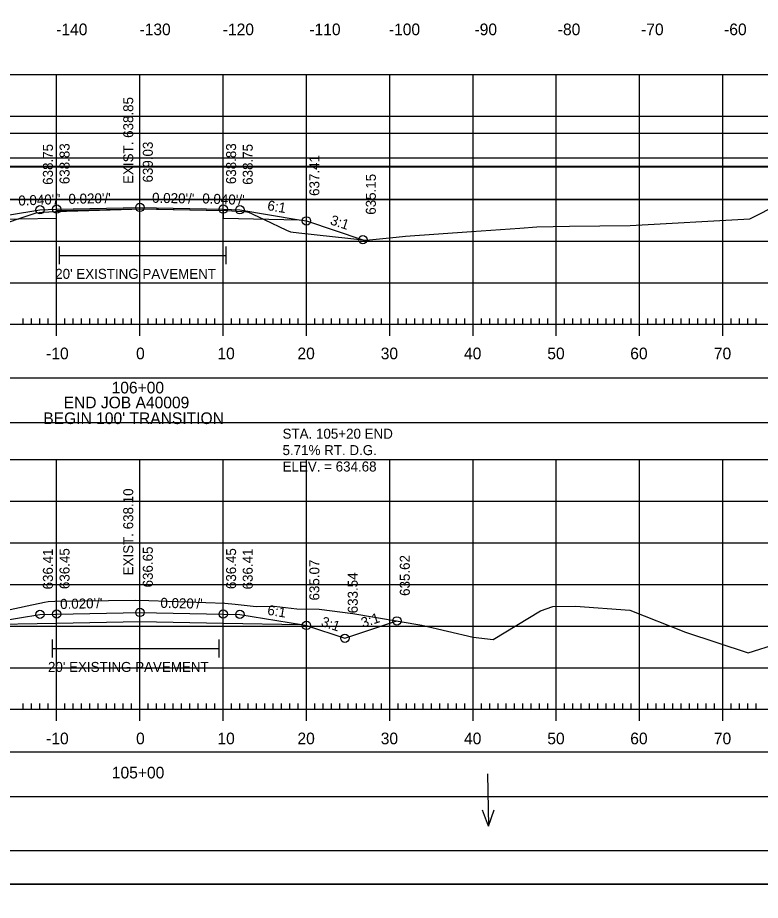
# Model space of a CAD drawing. Extents: x 1381471 to 1382703, y 370300 to 371487.
# Drawn here: x 1381990.1 to 1382079.3, y 370972.4 to 371078.4 of the extents above; entities that cross this region are included whole.
import ezdxf

# ---------------------------------------------------------------- set-up
doc = ezdxf.new("R2010")
doc.units = 0
for name, color, linetype in [('Level 16', 7, 'Continuous'), ('Level 18', 7, 'Continuous'), ('Level 2', 7, 'Continuous'), ('Level 20', 7, 'Continuous'), ('Level 21', 7, 'Continuous'), ('Level 22', 7, 'Continuous'), ('Level 26', 7, 'Continuous'), ('Level 4', 7, 'Continuous'), ('Level 40', 7, 'Continuous'), ('Level 41', 7, 'Continuous'), ('Level 42', 7, 'Continuous'), ('Level 45', 7, 'Continuous'), ('Level 5', 7, 'Continuous'), ('Level 6', 7, 'Continuous')]:
    doc.layers.add(name, color=color, linetype=linetype)

msp = doc.modelspace()

# ---------------------------------------------------------------- linework, layer by layer
at = {"layer": 'Level 16'}
for p, q in [((1381995.09, 371050.89), (1381995.09, 371048.75)), ((1382015.09, 371050.89), (1382015.09, 371048.75)), ((1381995.09, 371049.82), (1382015.09, 371049.82)), ((1381994.23, 371003.68), (1381994.23, 371001.54)), ((1382014.23, 371003.68), (1382014.23, 371001.54)), ((1381994.23, 371002.61), (1382014.23, 371002.61))]:
    msp.add_line(p, q, dxfattribs=at)
at = {"layer": 'Level 18'}
for points in [[(1381987.31, 371053.25), (1381990.38, 371054.28), (1381992.31, 371054.94), (1381993.02, 371055.01), (1381994.62, 371055.1), (1381998.64, 371055.21), (1382005.09, 371055.4), (1382012.74, 371055.24), (1382015.21, 371055.19), (1382017.6, 371055.05), (1382017.73, 371055.04), (1382019.71, 371054.11), (1382022.37, 371052.85), (1382022.84, 371052.64), (1382023.84, 371052.53), (1382031.92, 371051.66), (1382035.53, 371052.01), (1382036.68, 371052.13), (1382044.57, 371052.68), (1382050.4, 371053.09), (1382052.42, 371053.26), (1382056.35, 371053.34), (1382063.66, 371053.4), (1382078.02, 371054.19), (1382088.62, 371059.56)], [(1381986.4, 371006.7), (1381991.25, 371007.74), (1381993.31, 371008.17), (1381993.77, 371008.25), (1381994.56, 371008.27), (1382004.23, 371008.41), (1382005.83, 371008.36), (1382014.95, 371008.04), (1382016.22, 371007.92), (1382018.73, 371007.66), (1382020.88, 371007.68), (1382023.63, 371007.35), (1382026.3, 371007.31), (1382030.32, 371006.81), (1382038.62, 371005.42), (1382044.77, 371003.97), (1382047.2, 371003.69), (1382052.87, 371007.13), (1382054.36, 371007.64), (1382057.06, 371007.69), (1382063.6, 371007.21), (1382070.27, 371004.56), (1382077.82, 371002.09), (1382081.37, 371003.19)]]:
    msp.add_lwpolyline(points, dxfattribs=at)
at = {"layer": 'Level 2'}
for points in [[(1381985.66, 371054.11), (1381994.76, 371054.29), (1381994.77, 371055.21), (1382004.77, 371055.41), (1382014.77, 371055.2), (1382014.78, 371054.29), (1382023.91, 371054.1)], [(1381985.39, 371005.47), (1381994.77, 371005.66), (1382004.77, 371005.86), (1382014.77, 371005.66), (1382024.16, 371005.47)]]:
    msp.add_lwpolyline(points, dxfattribs=at)
at = {"layer": 'Level 20'}
for points in [[(1381973.41, 371053.43), (1381978.3, 371051.8), (1381984.77, 371053.96), (1381985.66, 371054.11), (1381992.77, 371055.29), (1381994.77, 371055.37), (1382004.77, 371055.57), (1382014.77, 371055.37), (1382016.77, 371055.29), (1382023.91, 371054.1), (1382024.77, 371053.96), (1382031.55, 371051.7)], [(1381968.79, 371006.89), (1381979.07, 371003.47), (1381984.77, 371005.37), (1381985.39, 371005.47), (1381992.77, 371006.7), (1381994.77, 371006.74), (1382004.77, 371006.94), (1382014.77, 371006.74), (1382016.77, 371006.7), (1382024.16, 371005.47), (1382024.77, 371005.37), (1382029.38, 371003.83), (1382035.63, 371005.92)]]:
    msp.add_lwpolyline(points, dxfattribs=at)
at = {"layer": 'Level 22'}
for p, q in [((1381864.77, 371071.54), (1382144.77, 371071.54)), ((1381994.77, 371041.54), (1381994.77, 371071.54)), ((1382004.77, 371041.54), (1382004.77, 371071.54)), ((1382014.77, 371041.54), (1382014.77, 371071.54)), ((1382024.77, 371041.54), (1382024.77, 371071.54)), ((1382034.77, 371041.54), (1382034.77, 371071.54)), ((1382044.77, 371041.54), (1382044.77, 371071.54)), ((1382054.77, 371041.54), (1382054.77, 371071.54)), ((1382064.77, 371041.54), (1382064.77, 371071.54)), ((1382074.77, 371041.54), (1382074.77, 371071.54)), ((1381864.77, 371066.54), (1382144.77, 371066.54)), ((1381864.77, 371061.54), (1382144.77, 371061.54)), ((1381864.77, 371056.54), (1382144.77, 371056.54)), ((1381864.77, 371051.54), (1382144.77, 371051.54)), ((1381864.77, 371046.54), (1382144.77, 371046.54)), ((1381864.77, 371041.54), (1382144.77, 371041.54)), ((1381864.77, 371025.3), (1382144.77, 371025.3)), ((1381994.77, 370995.3), (1381994.77, 371025.3)), ((1382004.77, 370995.3), (1382004.77, 371025.3)), ((1382014.77, 370995.3), (1382014.77, 371025.3)), ((1382024.77, 370995.3), (1382024.77, 371025.3)), ((1382034.77, 370995.3), (1382034.77, 371025.3)), ((1382044.77, 370995.3), (1382044.77, 371025.3)), ((1382054.77, 370995.3), (1382054.77, 371025.3)), ((1382064.77, 370995.3), (1382064.77, 371025.3)), ((1382074.77, 370995.3), (1382074.77, 371025.3)), ((1381864.77, 371020.3), (1382144.77, 371020.3)), ((1381864.77, 371015.3), (1382144.77, 371015.3)), ((1381864.77, 371010.3), (1382144.77, 371010.3)), ((1381864.77, 371005.3), (1382144.77, 371005.3)), ((1381864.77, 371000.3), (1382144.77, 371000.3)), ((1381864.77, 370995.3), (1382144.77, 370995.3))]:
    msp.add_line(p, q, dxfattribs=at)
at = {"layer": 'Level 26'}
for p, q in [((1381834.37, 370974.31), (1382167.7, 370974.31)), ((1381834.37, 370974.3), (1382167.7, 370974.3))]:
    msp.add_line(p, q, dxfattribs=at)
for points in [[(1381834.36, 371187.64), (1382167.7, 371187.64), (1382167.7, 370974.3), (1381834.36, 370974.3)], [(1382080.69, 371183.75), (1382100.31, 371183.75), (1382100.31, 371173.87), (1382116.42, 371173.87), (1382139.62, 371173.87), (1382139.62, 371141.2), (1382162.83, 371141.2), (1382162.95, 370978.29), (1381846.77, 370978.29), (1381846.77, 371183.75)], [(1381834.36, 370974.3), (1382167.7, 370974.3), (1382167.7, 370760.97), (1381834.36, 370760.97)]]:
    msp.add_lwpolyline(points, close=True, dxfattribs=at)
for centre in [(1381992.77, 371055.29), (1381994.77, 371055.37), (1382004.77, 371055.57), (1382014.77, 371055.37), (1382016.77, 371055.29), (1382024.77, 371053.96), (1382031.55, 371051.7), (1381992.77, 371006.7), (1381994.77, 371006.74), (1382004.77, 371006.94), (1382014.77, 371006.74), (1382016.77, 371006.7), (1382024.77, 371005.37), (1382035.63, 371005.92), (1382029.38, 371003.83), (1382029.38, 371003.83)]:
    msp.add_circle(centre, 0.5, dxfattribs=at)
at = {"layer": 'Level 4'}
for p, q in [((1381994.77, 371040.14), (1381994.77, 371042.94)), ((1382004.77, 371040.14), (1382004.77, 371042.94)), ((1382014.77, 371040.14), (1382014.77, 371042.94)), ((1382024.77, 371040.14), (1382024.77, 371042.94)), ((1382034.77, 371040.14), (1382034.77, 371042.94)), ((1382044.77, 371040.14), (1382044.77, 371042.94)), ((1382054.77, 371040.14), (1382054.77, 371042.94)), ((1382064.77, 371040.14), (1382064.77, 371042.94)), ((1382074.77, 371040.14), (1382074.77, 371042.94)), ((1381990.77, 371041.54), (1381990.77, 371042.24)), ((1381991.77, 371041.54), (1381991.77, 371042.24)), ((1381992.77, 371041.54), (1381992.77, 371042.24)), ((1381993.77, 371041.54), (1381993.77, 371042.24)), ((1381995.77, 371041.54), (1381995.77, 371042.24)), ((1381996.77, 371041.54), (1381996.77, 371042.24)), ((1381997.77, 371041.54), (1381997.77, 371042.24)), ((1381998.77, 371041.54), (1381998.77, 371042.24)), ((1381999.77, 371041.54), (1381999.77, 371042.24)), ((1382000.77, 371041.54), (1382000.77, 371042.24)), ((1382001.77, 371041.54), (1382001.77, 371042.24)), ((1382002.77, 371041.54), (1382002.77, 371042.24)), ((1382003.77, 371041.54), (1382003.77, 371042.24)), ((1382005.77, 371041.54), (1382005.77, 371042.24)), ((1382006.77, 371041.54), (1382006.77, 371042.24)), ((1382007.77, 371041.54), (1382007.77, 371042.24)), ((1382008.77, 371041.54), (1382008.77, 371042.24)), ((1382009.77, 371041.54), (1382009.77, 371042.24)), ((1382010.77, 371041.54), (1382010.77, 371042.24)), ((1382011.77, 371041.54), (1382011.77, 371042.24)), ((1382012.77, 371041.54), (1382012.77, 371042.24)), ((1382013.77, 371041.54), (1382013.77, 371042.24)), ((1382015.77, 371041.54), (1382015.77, 371042.24)), ((1382016.77, 371041.54), (1382016.77, 371042.24)), ((1382017.77, 371041.54), (1382017.77, 371042.24)), ((1382018.77, 371041.54), (1382018.77, 371042.24)), ((1382019.77, 371041.54), (1382019.77, 371042.24)), ((1382020.77, 371041.54), (1382020.77, 371042.24)), ((1382021.77, 371041.54), (1382021.77, 371042.24)), ((1382022.77, 371041.54), (1382022.77, 371042.24)), ((1382023.77, 371041.54), (1382023.77, 371042.24)), ((1382025.77, 371041.54), (1382025.77, 371042.24)), ((1382026.77, 371041.54), (1382026.77, 371042.24)), ((1382027.77, 371041.54), (1382027.77, 371042.24)), ((1382028.77, 371041.54), (1382028.77, 371042.24)), ((1382029.77, 371041.54), (1382029.77, 371042.24)), ((1382030.77, 371041.54), (1382030.77, 371042.24)), ((1382031.77, 371041.54), (1382031.77, 371042.24)), ((1382032.77, 371041.54), (1382032.77, 371042.24)), ((1382033.77, 371041.54), (1382033.77, 371042.24)), ((1382035.77, 371041.54), (1382035.77, 371042.24)), ((1382036.77, 371041.54), (1382036.77, 371042.24)), ((1382037.77, 371041.54), (1382037.77, 371042.24)), ((1382038.77, 371041.54), (1382038.77, 371042.24)), ((1382039.77, 371041.54), (1382039.77, 371042.24)), ((1382040.77, 371041.54), (1382040.77, 371042.24)), ((1382041.77, 371041.54), (1382041.77, 371042.24)), ((1382042.77, 371041.54), (1382042.77, 371042.24)), ((1382043.77, 371041.54), (1382043.77, 371042.24)), ((1382045.77, 371041.54), (1382045.77, 371042.24)), ((1382046.77, 371041.54), (1382046.77, 371042.24)), ((1382047.77, 371041.54), (1382047.77, 371042.24)), ((1382048.77, 371041.54), (1382048.77, 371042.24)), ((1382049.77, 371041.54), (1382049.77, 371042.24)), ((1382050.77, 371041.54), (1382050.77, 371042.24)), ((1382051.77, 371041.54), (1382051.77, 371042.24)), ((1382052.77, 371041.54), (1382052.77, 371042.24)), ((1382053.77, 371041.54), (1382053.77, 371042.24)), ((1382055.77, 371041.54), (1382055.77, 371042.24)), ((1382056.77, 371041.54), (1382056.77, 371042.24)), ((1382057.77, 371041.54), (1382057.77, 371042.24)), ((1382058.77, 371041.54), (1382058.77, 371042.24)), ((1382059.77, 371041.54), (1382059.77, 371042.24)), ((1382060.77, 371041.54), (1382060.77, 371042.24)), ((1382061.77, 371041.54), (1382061.77, 371042.24)), ((1382062.77, 371041.54), (1382062.77, 371042.24)), ((1382063.77, 371041.54), (1382063.77, 371042.24)), ((1382065.77, 371041.54), (1382065.77, 371042.24)), ((1382066.77, 371041.54), (1382066.77, 371042.24)), ((1382067.77, 371041.54), (1382067.77, 371042.24)), ((1382068.77, 371041.54), (1382068.77, 371042.24)), ((1382069.77, 371041.54), (1382069.77, 371042.24)), ((1382070.77, 371041.54), (1382070.77, 371042.24)), ((1382071.77, 371041.54), (1382071.77, 371042.24)), ((1382072.77, 371041.54), (1382072.77, 371042.24)), ((1382073.77, 371041.54), (1382073.77, 371042.24)), ((1382075.77, 371041.54), (1382075.77, 371042.24)), ((1382076.77, 371041.54), (1382076.77, 371042.24)), ((1382077.77, 371041.54), (1382077.77, 371042.24)), ((1382078.77, 371041.54), (1382078.77, 371042.24)), ((1381864.77, 371041.54), (1382144.77, 371041.54)), ((1381994.77, 370993.9), (1381994.77, 370996.7)), ((1382004.77, 370993.9), (1382004.77, 370996.7)), ((1382014.77, 370993.9), (1382014.77, 370996.7)), ((1382024.77, 370993.9), (1382024.77, 370996.7)), ((1382034.77, 370993.9), (1382034.77, 370996.7)), ((1382044.77, 370993.9), (1382044.77, 370996.7)), ((1382054.77, 370993.9), (1382054.77, 370996.7)), ((1382064.77, 370993.9), (1382064.77, 370996.7)), ((1382074.77, 370993.9), (1382074.77, 370996.7)), ((1381864.77, 370995.3), (1382144.77, 370995.3)), ((1381990.77, 370995.3), (1381990.77, 370996)), ((1381991.77, 370995.3), (1381991.77, 370996)), ((1381992.77, 370995.3), (1381992.77, 370996)), ((1381993.77, 370995.3), (1381993.77, 370996)), ((1381995.77, 370995.3), (1381995.77, 370996)), ((1381996.77, 370995.3), (1381996.77, 370996)), ((1381997.77, 370995.3), (1381997.77, 370996)), ((1381998.77, 370995.3), (1381998.77, 370996)), ((1381999.77, 370995.3), (1381999.77, 370996)), ((1382000.77, 370995.3), (1382000.77, 370996)), ((1382001.77, 370995.3), (1382001.77, 370996)), ((1382002.77, 370995.3), (1382002.77, 370996)), ((1382003.77, 370995.3), (1382003.77, 370996)), ((1382005.77, 370995.3), (1382005.77, 370996)), ((1382006.77, 370995.3), (1382006.77, 370996)), ((1382007.77, 370995.3), (1382007.77, 370996)), ((1382008.77, 370995.3), (1382008.77, 370996)), ((1382009.77, 370995.3), (1382009.77, 370996)), ((1382010.77, 370995.3), (1382010.77, 370996)), ((1382011.77, 370995.3), (1382011.77, 370996)), ((1382012.77, 370995.3), (1382012.77, 370996)), ((1382013.77, 370995.3), (1382013.77, 370996)), ((1382015.77, 370995.3), (1382015.77, 370996)), ((1382016.77, 370995.3), (1382016.77, 370996)), ((1382017.77, 370995.3), (1382017.77, 370996)), ((1382018.77, 370995.3), (1382018.77, 370996)), ((1382019.77, 370995.3), (1382019.77, 370996)), ((1382020.77, 370995.3), (1382020.77, 370996)), ((1382021.77, 370995.3), (1382021.77, 370996)), ((1382022.77, 370995.3), (1382022.77, 370996)), ((1382023.77, 370995.3), (1382023.77, 370996)), ((1382025.77, 370995.3), (1382025.77, 370996)), ((1382026.77, 370995.3), (1382026.77, 370996)), ((1382027.77, 370995.3), (1382027.77, 370996)), ((1382028.77, 370995.3), (1382028.77, 370996)), ((1382029.77, 370995.3), (1382029.77, 370996)), ((1382030.77, 370995.3), (1382030.77, 370996)), ((1382031.77, 370995.3), (1382031.77, 370996)), ((1382032.77, 370995.3), (1382032.77, 370996)), ((1382033.77, 370995.3), (1382033.77, 370996)), ((1382035.77, 370995.3), (1382035.77, 370996)), ((1382036.77, 370995.3), (1382036.77, 370996)), ((1382037.77, 370995.3), (1382037.77, 370996)), ((1382038.77, 370995.3), (1382038.77, 370996)), ((1382039.77, 370995.3), (1382039.77, 370996)), ((1382040.77, 370995.3), (1382040.77, 370996)), ((1382041.77, 370995.3), (1382041.77, 370996)), ((1382042.77, 370995.3), (1382042.77, 370996)), ((1382043.77, 370995.3), (1382043.77, 370996)), ((1382045.77, 370995.3), (1382045.77, 370996)), ((1382046.77, 370995.3), (1382046.77, 370996)), ((1382047.77, 370995.3), (1382047.77, 370996)), ((1382048.77, 370995.3), (1382048.77, 370996)), ((1382049.77, 370995.3), (1382049.77, 370996)), ((1382050.77, 370995.3), (1382050.77, 370996)), ((1382051.77, 370995.3), (1382051.77, 370996)), ((1382052.77, 370995.3), (1382052.77, 370996)), ((1382053.77, 370995.3), (1382053.77, 370996)), ((1382055.77, 370995.3), (1382055.77, 370996)), ((1382056.77, 370995.3), (1382056.77, 370996)), ((1382057.77, 370995.3), (1382057.77, 370996)), ((1382058.77, 370995.3), (1382058.77, 370996)), ((1382059.77, 370995.3), (1382059.77, 370996)), ((1382060.77, 370995.3), (1382060.77, 370996)), ((1382061.77, 370995.3), (1382061.77, 370996)), ((1382062.77, 370995.3), (1382062.77, 370996)), ((1382063.77, 370995.3), (1382063.77, 370996)), ((1382065.77, 370995.3), (1382065.77, 370996)), ((1382066.77, 370995.3), (1382066.77, 370996)), ((1382067.77, 370995.3), (1382067.77, 370996)), ((1382068.77, 370995.3), (1382068.77, 370996)), ((1382069.77, 370995.3), (1382069.77, 370996)), ((1382070.77, 370995.3), (1382070.77, 370996)), ((1382071.77, 370995.3), (1382071.77, 370996)), ((1382072.77, 370995.3), (1382072.77, 370996)), ((1382073.77, 370995.3), (1382073.77, 370996)), ((1382075.77, 370995.3), (1382075.77, 370996)), ((1382076.77, 370995.3), (1382076.77, 370996)), ((1382077.77, 370995.3), (1382077.77, 370996)), ((1382078.77, 370995.3), (1382078.77, 370996))]:
    msp.add_line(p, q, dxfattribs=at)
at = {"layer": 'Level 40'}
for p, q in [((1382046.51, 370987.55), (1382046.63, 370981.27)), ((1382046.63, 370981.27), (1382045.89, 370983.18)), ((1382046.63, 370981.27), (1382047.29, 370983.21))]:
    msp.add_line(p, q, dxfattribs=at)
at = {"layer": 'Level 45'}
for p, q in [((1382294.79, 371064.46), (1381978.61, 371064.46)), ((1381966.21, 371060.48), (1382299.55, 371060.48)), ((1381966.21, 371060.47), (1382299.55, 371060.47)), ((1381978.61, 371056.58), (1382294.79, 371056.58))]:
    msp.add_line(p, q, dxfattribs=at)
for points in [[(1381966.21, 371273.81), (1382299.55, 371273.81), (1382299.55, 371060.48), (1381966.21, 371060.48)], [(1382212.53, 371269.92), (1382232.15, 371269.92), (1382232.15, 371260.04), (1382248.27, 371260.04), (1382271.46, 371260.04), (1382271.46, 371235.71), (1382294.79, 371235.71), (1382294.79, 371064.46), (1381978.61, 371064.46), (1381978.61, 371269.92)], [(1381966.21, 371060.47), (1382299.55, 371060.47), (1382299.55, 370847.14), (1381966.21, 370847.14)], [(1382212.53, 371056.58), (1382232.15, 371056.58), (1382232.15, 371046.7), (1382248.27, 371046.7), (1382271.46, 371046.7), (1382271.46, 371022.37), (1382294.79, 371022.37), (1382294.79, 370851.12), (1381978.61, 370851.12), (1381978.61, 371056.58)]]:
    msp.add_lwpolyline(points, close=True, dxfattribs=at)
at = {"layer": 'Level 6'}
msp.add_line((1382162.95, 370978.29), (1381846.77, 370978.29), dxfattribs=at)
for points in [[(1381850.41, 371029.76), (1382159.14, 371029.76), (1382159.14, 371035.09), (1381850.41, 371035.09)], [(1381850.41, 370984.82), (1382159.14, 370984.82), (1382159.14, 370990.14), (1381850.41, 370990.14)]]:
    msp.add_lwpolyline(points, close=True, dxfattribs=at)

# ---------------------------------------------------------------- texts
at = {"layer": 'Level 21'}
for p in [(1381994.6, 371047), (1381993.73, 370999.79)]:
    msp.add_text("20' EXISTING PAVEMENT", height=1.2, dxfattribs=at).set_placement(p)
at = {"layer": 'Level 41'}
for s, p in [('EXIST. 638.85', (1382003.97, 371058.4)), ('638.75', (1381994.32, 371058.29)), ('638.83', (1381996.32, 371058.37)), ('639.03', (1382006.32, 371058.57)), ('638.83', (1382016.32, 371058.37)), ('638.75', (1382018.32, 371058.29)), ('637.41', (1382026.32, 371056.96)), ('635.15', (1382033.1, 371054.7)), ('EXIST. 638.10', (1382003.97, 371011.39)), ('636.41', (1381994.32, 371009.7)), ('636.45', (1381996.32, 371009.74)), ('636.65', (1382006.32, 371009.94)), ('636.45', (1382016.32, 371009.74)), ('636.41', (1382018.32, 371009.7)), ('635.07', (1382026.32, 371008.37)), ('635.62', (1382037.18, 371008.92)), ('633.54', (1382030.93, 371006.83))]:
    msp.add_text(s, height=1.2, rotation=90, dxfattribs=at).set_placement(p)
at = {"layer": 'Level 42'}
for s, rotation, p in [("0.040'/'", 2.2906, (1381990.19, 371055.79)), ("0.020'/'", 1.1458, (1381996.2, 371056)), ("0.020'/'", 358.8542, (1382006.22, 371056.14)), ("0.040'/'", 357.7094, (1382012.24, 371056.07)), ('6:1', 350.5377, (1382020.01, 371055.26)), ('3:1', 341.5651, (1382027.53, 371053.57)), ("0.020'/'", 1.1458, (1381995.2, 371007.35)), ("0.020'/'", 358.8542, (1382007.22, 371007.49)), ('6:1', 350.5375, (1382020.01, 371006.67)), ('3:1', 18.4349, (1382031.56, 371005.09)), ('3:1', 341.5651, (1382026.44, 371005.34))]:
    msp.add_text(s, height=1.2, rotation=rotation, dxfattribs=at).set_placement(p)
at = {"layer": 'Level 45'}
for s, p in [('-140', (1381994.72, 371076.26)), ('-130', (1382004.72, 371076.26)), ('-120', (1382014.72, 371076.26)), ('-110', (1382025.12, 371076.26)), ('-100', (1382034.67, 371076.26)), ('-90', (1382044.95, 371076.26)), ('-80', (1382054.95, 371076.26)), ('-70', (1382064.95, 371076.26)), ('-60', (1382074.92, 371076.26))]:
    msp.add_text(s, height=1.4, dxfattribs=at).set_placement(p)
at = {"layer": 'Level 5'}
for s, height, p in [('-10', 1.4, (1381993.51, 371037.34)), ('0', 1.4, (1382004.31, 371037.34)), ('10', 1.4, (1382014.08, 371037.34)), ('20', 1.4, (1382023.69, 371037.34)), ('30', 1.4, (1382033.69, 371037.34)), ('40', 1.4, (1382043.69, 371037.34)), ('50', 1.4, (1382053.69, 371037.34)), ('60', 1.4, (1382063.65, 371037.34)), ('70', 1.4, (1382073.69, 371037.34)), ('106+00', 1.4, (1382001.37, 371033.24)), ('END JOB A40009', 1.4, (1381995.61, 371031.45)), ("BEGIN 100' TRANSITION", 1.4, (1381993.17, 371029.56)), ('STA. 105+20 END', 1.2, (1382021.9, 371027.8)), ('5.71% RT. D.G. ', 1.2, (1382021.9, 371025.83)), ('ELEV. = 634.68', 1.2, (1382021.9, 371023.86)), ('-10', 1.4, (1381993.51, 370991.1)), ('0', 1.4, (1382004.31, 370991.1)), ('10', 1.4, (1382014.08, 370991.1)), ('20', 1.4, (1382023.69, 370991.1)), ('30', 1.4, (1382033.69, 370991.1)), ('40', 1.4, (1382043.69, 370991.1)), ('50', 1.4, (1382053.69, 370991.1)), ('60', 1.4, (1382063.65, 370991.1)), ('70', 1.4, (1382073.69, 370991.1)), ('105+00', 1.4, (1382001.4, 370987))]:
    msp.add_text(s, height=height, dxfattribs=at).set_placement(p)

doc.saveas('drawing.dxf')
